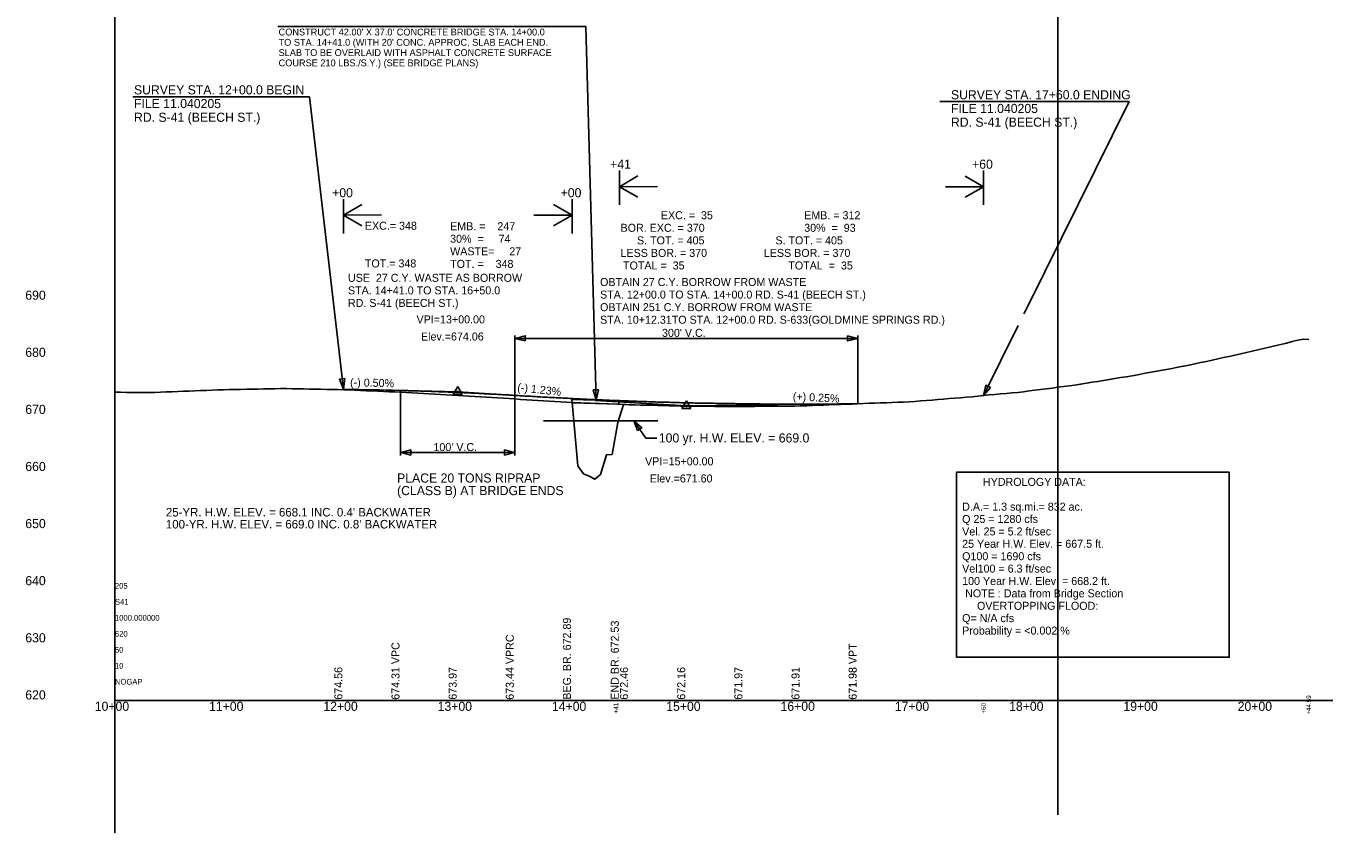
# Model space of a CAD drawing. Extents: x 16382402 to 16388022, y 46194326 to 46202918.
# Drawn here: x 16384274 to 16385409, y 46195513 to 46196212 of the extents above; entities that cross this region are included whole.
import ezdxf

# ---------------------------------------------------------------- set-up
doc = ezdxf.new("R2010")
doc.units = 0
for name, color, linetype in [('Default', 7, 'Continuous'), ('RD_DDB_ElevTX', 7, 'Continuous'), ('RD_DDB_GradeTX', 7, 'Continuous'), ('RD_DDB_Profile_EX', 7, 'Continuous'), ('RD_DDB_Profile_Lbl', 7, 'Continuous'), ('RD_DDB_Profile_PR', 7, 'Continuous'), ('RD_DDB_StaTX', 7, 'Continuous'), ('RD_DDB_StripGrade', 7, 'Continuous'), ('RD_DDB_VCLbl', 7, 'Continuous'), ('RD_EX_Bridge', 7, 'Continuous'), ('RD_GPK_Profile_Cell', 7, 'Continuous'), ('RD_HC_Data', 7, 'Continuous'), ('RD_PD_Final_TX', 7, 'Continuous'), ('RD_TX_Drainage', 7, 'Continuous'), ('RD_TX_Misc1', 7, 'Continuous'), ('RD_TX_Profile', 7, 'Continuous')]:
    doc.layers.add(name, color=color, linetype=linetype)

msp = doc.modelspace()

# ---------------------------------------------------------------- linework, layer by layer
at = {"layer": 'Default'}
for p, q in [((16384792.8, 46196054.9), (16384792.8, 46196084.9)), ((16384808.8, 46196080.2), (16384792.8, 46196070.8)), ((16385095.2, 46196080.1), (16385111.4, 46196070.8)), ((16385111.4, 46196054.9), (16385111.4, 46196084.9)), ((16384826.1, 46196071.1), (16384792.8, 46196070.8)), ((16384808.9, 46196061.6), (16384792.8, 46196070.8)), ((16385078, 46196070.8), (16385111.4, 46196070.8)), ((16385095.2, 46196061.5), (16385111.4, 46196070.8)), ((16384551.4, 46196029.9), (16384551.4, 46196059.9)), ((16384567.4, 46196055.2), (16384551.4, 46196045.8)), ((16384735.2, 46196055.1), (16384751.4, 46196045.8)), ((16384751.4, 46196029.9), (16384751.4, 46196059.9)), ((16384584.7, 46196046.1), (16384551.4, 46196045.8)), ((16384567.5, 46196036.6), (16384551.4, 46196045.8)), ((16384718, 46196045.8), (16384751.4, 46196045.8)), ((16384735.2, 46196036.5), (16384751.4, 46196045.8)), ((16384826.4, 46195865.8), (16384726.4, 46195865.8)), ((16384816, 46195850.6), (16384805.4, 46195865.8)), ((16384825.5, 46195850.7), (16384816, 46195850.6))]:
    msp.add_line(p, q, dxfattribs=at)
at = {"layer": 'RD_DDB_GradeTX'}
for p, q in [((16384571.4, 46195893.1), (16384651.4, 46195891.1)), ((16384731.2, 46195886.2), (16384651.4, 46195891.1)), ((16384771.5, 46195883.7), (16384851.4, 46195878.8)), ((16384931.3, 46195879.8), (16384851.4, 46195878.8))]:
    msp.add_line(p, q, dxfattribs=at)
at = {"layer": 'RD_DDB_Profile_EX'}
for points in [[(16384851.4, 46195878.7), (16384856.4, 46195878.6), (16384861.4, 46195878.6), (16384866.4, 46195878.6), (16384871.4, 46195878.5), (16384876.4, 46195878.3), (16384881.4, 46195878.3), (16384886.4, 46195878.3), (16384891.4, 46195878.3), (16384896.4, 46195878.3), (16384901.4, 46195878.3), (16384906.4, 46195878.4), (16384911.4, 46195878.4), (16384916.4, 46195878.5), (16384921.4, 46195878.5), (16384926.4, 46195878.4), (16384931.4, 46195878.5), (16384936.4, 46195878.6), (16384941.4, 46195878.6), (16384946.4, 46195878.7), (16384951.4, 46195878.8), (16384956.4, 46195879), (16384961.4, 46195879.2), (16384966.4, 46195879.4), (16384971.4, 46195879.6), (16384976.4, 46195879.8), (16384981.4, 46195880), (16384986.4, 46195880.1), (16384991.4, 46195880.3), (16384996.4, 46195880.5), (16385001.4, 46195880.7), (16385006.4, 46195880.9), (16385011.4, 46195881.1), (16385016.4, 46195881.3), (16385021.4, 46195881.4), (16385026.4, 46195881.6), (16385031.4, 46195881.8), (16385036.4, 46195882), (16385041.4, 46195882.2), (16385046.4, 46195882.4), (16385051.4, 46195882.8), (16385056.4, 46195883.2), (16385061.4, 46195883.6), (16385066.4, 46195884), (16385071.4, 46195884.4), (16385076.4, 46195884.8), (16385081.4, 46195885.2), (16385086.4, 46195885.6), (16385091.4, 46195886), (16385096.4, 46195886.4), (16385101.4, 46195886.9), (16385106.4, 46195887.4), (16385111.4, 46195887.9), (16385116.4, 46195888.4), (16385121.4, 46195888.8), (16385126.4, 46195889.3), (16385131.4, 46195889.8), (16385136.4, 46195890.2), (16385141.4, 46195890.7), (16385146.4, 46195891.3), (16385151.4, 46195891.9), (16385156.4, 46195892.6), (16385161.4, 46195893.2), (16385166.4, 46195893.9), (16385171.4, 46195894.5), (16385176.4, 46195895.2), (16385181.4, 46195895.8), (16385186.4, 46195896.4), (16385191.4, 46195897.1), (16385196.4, 46195897.8), (16385201.4, 46195898.7), (16385206.4, 46195899.5), (16385211.4, 46195900.3), (16385216.4, 46195901.1), (16385221.4, 46195901.9), (16385226.4, 46195902.8), (16385231.4, 46195903.6), (16385236.4, 46195904.4), (16385241.4, 46195905.2), (16385246.4, 46195906.1), (16385251.4, 46195907.1), (16385256.4, 46195908), (16385261.4, 46195908.9), (16385266.4, 46195909.9), (16385271.4, 46195910.8), (16385276.4, 46195911.7), (16385281.4, 46195912.7), (16385286.4, 46195913.6), (16385291.4, 46195914.6), (16385296.4, 46195915.7), (16385301.4, 46195916.8), (16385306.4, 46195917.8), (16385311.4, 46195918.9), (16385316.4, 46195920), (16385321.4, 46195921.1), (16385326.4, 46195922.2), (16385331.4, 46195923.3), (16385336.4, 46195924.3), (16385341.4, 46195925.5), (16385346.4, 46195926.7), (16385351.4, 46195927.9)], [(16385351.4, 46195927.9), (16385356.4, 46195929.1), (16385361.4, 46195930.3), (16385366.4, 46195931.5), (16385371.4, 46195932.7), (16385376.4, 46195933.9), (16385381.4, 46195935.1), (16385386.4, 46195936.3), (16385391.4, 46195937.2), (16385395.9, 46195937.1)], [(16384351.4, 46195890.8), (16384356.4, 46195890.8), (16384361.4, 46195890.7), (16384366.4, 46195890.7), (16384371.4, 46195890.7), (16384376.4, 46195890.6), (16384381.4, 46195890.6), (16384386.4, 46195890.7), (16384391.4, 46195890.9), (16384396.4, 46195891.1), (16384401.4, 46195891.2), (16384406.4, 46195891.4), (16384411.4, 46195891.6), (16384416.4, 46195891.8), (16384421.4, 46195892), (16384426.4, 46195892.2), (16384431.4, 46195892.4), (16384436.4, 46195892.6), (16384441.4, 46195892.8), (16384446.4, 46195893), (16384451.4, 46195893.2), (16384456.4, 46195893.3), (16384461.4, 46195893.3), (16384466.4, 46195893.4), (16384471.4, 46195893.5), (16384476.4, 46195893.6), (16384481.4, 46195893.7), (16384486.4, 46195893.8), (16384491.4, 46195893.9), (16384496.4, 46195894), (16384501.4, 46195894), (16384506.4, 46195893.9), (16384511.4, 46195893.8), (16384516.4, 46195893.7), (16384521.4, 46195893.6), (16384526.4, 46195893.5), (16384531.4, 46195893.4), (16384536.4, 46195893.3), (16384541.4, 46195893.2), (16384546.4, 46195893.1), (16384551.4, 46195893), (16384556.4, 46195892.8), (16384561.4, 46195892.6), (16384566.4, 46195892.4), (16384571.4, 46195892.1), (16384576.4, 46195891.9), (16384581.4, 46195891.7), (16384586.4, 46195891.5), (16384591.4, 46195891.3), (16384596.4, 46195891.1), (16384601.4, 46195890.9), (16384606.4, 46195890.6), (16384611.4, 46195890.3), (16384616.4, 46195890), (16384621.4, 46195889.7), (16384626.4, 46195889.4), (16384631.4, 46195889.1), (16384636.4, 46195888.8), (16384641.4, 46195888.5), (16384646.4, 46195888.2), (16384651.4, 46195887.9), (16384656.4, 46195887.8), (16384661.4, 46195887.5), (16384666.4, 46195887.2), (16384671.4, 46195886.8), (16384676.4, 46195886.6), (16384681.4, 46195886.3), (16384686.4, 46195885.9), (16384691.4, 46195885.6), (16384696.4, 46195885.2), (16384701.4, 46195884.9), (16384706.4, 46195884.5), (16384711.4, 46195884.2), (16384716.4, 46195883.9), (16384721.4, 46195883.6), (16384726.4, 46195883.2), (16384731.4, 46195882.9), (16384736.4, 46195882.6), (16384741.4, 46195882.3), (16384746.4, 46195882), (16384751.4, 46195881.7), (16384756.4, 46195826.3), (16384761.4, 46195819.5), (16384766.4, 46195817.3), (16384771.4, 46195814.6), (16384776.4, 46195818.8), (16384781.4, 46195836), (16384786.4, 46195836.4), (16384791.4, 46195864.3), (16384796.4, 46195880.1), (16384801.4, 46195879.9), (16384806.4, 46195879.8), (16384811.4, 46195879.6), (16384816.4, 46195879.5), (16384821.4, 46195879.5), (16384826.4, 46195879.3), (16384831.4, 46195879.2), (16384836.4, 46195879), (16384841.4, 46195878.8), (16384846.4, 46195878.7), (16384851.4, 46195878.7)]]:
    msp.add_lwpolyline(points, dxfattribs=at)
at = {"layer": 'RD_DDB_Profile_PR'}
msp.add_line((16384551.4, 46195893.6), (16384601.4, 46195892.4), dxfattribs=at)
for points in [[(16384601.4, 46195892.4), (16384603.4, 46195892.3), (16384605.4, 46195892.3), (16384607.4, 46195892.2), (16384609.4, 46195892.1), (16384611.4, 46195892.1), (16384613.4, 46195892), (16384615.4, 46195892), (16384617.4, 46195891.9), (16384619.4, 46195891.8), (16384621.4, 46195891.8), (16384623.4, 46195891.7), (16384625.4, 46195891.6), (16384627.4, 46195891.6), (16384629.4, 46195891.5), (16384631.4, 46195891.4), (16384633.4, 46195891.4), (16384635.4, 46195891.3), (16384637.4, 46195891.2), (16384639.4, 46195891.1), (16384641.4, 46195891.1), (16384643.4, 46195891), (16384645.4, 46195890.9), (16384647.4, 46195890.8), (16384649.4, 46195890.7), (16384651.4, 46195890.6), (16384653.4, 46195890.6), (16384655.4, 46195890.5), (16384657.4, 46195890.4), (16384659.4, 46195890.3), (16384661.4, 46195890.2), (16384663.4, 46195890.1), (16384665.4, 46195890), (16384667.4, 46195889.9), (16384669.4, 46195889.8), (16384671.4, 46195889.7), (16384673.4, 46195889.6), (16384675.4, 46195889.5), (16384677.4, 46195889.4), (16384679.4, 46195889.3), (16384681.4, 46195889.2), (16384683.4, 46195889.1), (16384685.4, 46195889), (16384687.4, 46195888.8), (16384689.4, 46195888.7), (16384691.4, 46195888.6), (16384693.4, 46195888.5), (16384695.4, 46195888.4), (16384697.4, 46195888.3), (16384699.4, 46195888.1), (16384701.4, 46195888)], [(16384701.4, 46195888), (16384707.4, 46195887.7), (16384713.4, 46195887.3), (16384719.4, 46195887), (16384725.4, 46195886.6), (16384731.4, 46195886.3), (16384737.4, 46195886), (16384743.4, 46195885.7), (16384749.4, 46195885.4), (16384755.4, 46195885.1), (16384761.4, 46195884.8), (16384767.4, 46195884.5), (16384773.4, 46195884.2), (16384779.4, 46195884), (16384785.4, 46195883.7), (16384791.4, 46195883.5), (16384797.4, 46195883.3), (16384803.4, 46195883), (16384809.4, 46195882.8), (16384815.4, 46195882.6), (16384821.4, 46195882.4), (16384827.4, 46195882.2), (16384833.4, 46195882.1), (16384839.4, 46195881.9), (16384845.4, 46195881.7), (16384851.4, 46195881.6), (16384857.4, 46195881.4), (16384863.4, 46195881.3), (16384869.4, 46195881.2), (16384875.4, 46195881.1), (16384881.4, 46195881), (16384887.4, 46195880.9), (16384893.4, 46195880.8), (16384899.4, 46195880.7), (16384905.4, 46195880.6), (16384911.4, 46195880.6), (16384917.4, 46195880.5), (16384923.4, 46195880.5), (16384929.4, 46195880.4), (16384935.4, 46195880.4), (16384941.4, 46195880.4), (16384947.4, 46195880.4), (16384953.4, 46195880.4), (16384959.4, 46195880.4), (16384965.4, 46195880.4), (16384971.4, 46195880.4), (16384977.4, 46195880.5), (16384983.4, 46195880.5), (16384989.4, 46195880.6), (16384995.4, 46195880.6), (16385001.4, 46195880.7)]]:
    msp.add_spline(points, degree=3, dxfattribs=at)
at = {"layer": 'RD_DDB_VCLbl'}
for p, q in [((16384701.4, 46195940.5), (16384701.4, 46195888)), ((16385001.4, 46195940.5), (16385001.4, 46195880.7)), ((16384701.4, 46195938), (16385001.4, 46195938)), ((16384601.4, 46195835.5), (16384601.4, 46195892.4)), ((16384701.4, 46195835.5), (16384701.4, 46195888)), ((16384601.4, 46195838), (16384701.4, 46195838))]:
    msp.add_line(p, q, dxfattribs=at)
at = {"layer": 'RD_EX_Bridge'}
for p, q in [((16384493.9, 46196211), (16384763.3, 46196211)), ((16384772.5, 46195883.9), (16384763.3, 46196211)), ((16384751.3, 46195884.5), (16384792.4, 46195883.4)), ((16384751.4, 46195881.5), (16384751.3, 46195884.5)), ((16384792.4, 46195883.4), (16384792.4, 46195880.3)), ((16384792.4, 46195880.3), (16384751.4, 46195881.5))]:
    msp.add_line(p, q, dxfattribs=at)
at = {"layer": 'RD_GPK_Profile_Cell'}
for p, q in [((16384351.4, 46195620.8), (16384351.4, 46196870.8)), ((16385176.4, 46196770.8), (16385176.4, 46195520.8)), ((16384351.4, 46195620.8), (16385651.4, 46195620.8)), ((16384351.4, 46195620.8), (16384351.4, 46194370.8))]:
    msp.add_line(p, q, dxfattribs=at)
at = {"layer": 'RD_HC_Data'}
for p, q in [((16384647.4, 46195888.8), (16384651.4, 46195895.7)), ((16384651.4, 46195895.7), (16384655.3, 46195888.8)), ((16384647.4, 46195888.8), (16384655.3, 46195888.8)), ((16384847.4, 46195876.5), (16384851.4, 46195883.4)), ((16384851.4, 46195883.4), (16384855.3, 46195876.5)), ((16384847.4, 46195876.5), (16384855.3, 46195876.5))]:
    msp.add_line(p, q, dxfattribs=at)
for centre in [(16384651.4, 46195891.1), (16384851.4, 46195878.8)]:
    msp.add_circle(centre, 0.529, dxfattribs=at)
at = {"layer": 'RD_PD_Final_TX'}
for p, q in [((16384367.2, 46196149.5), (16384521.8, 46196149.5)), ((16384551.3, 46195893.6), (16384521.8, 46196149.5)), ((16385073.3, 46196145.3), (16385238.9, 46196145.3)), ((16385150.2, 46195966.3), (16385238.9, 46196145.3)), ((16385146.8, 46195959.4), (16385150.2, 46195966.3)), ((16385111.4, 46195887.9), (16385141.8, 46195949.3))]:
    msp.add_line(p, q, dxfattribs=at)
at = {"layer": 'RD_TX_Drainage'}
for points in [[(16384710.4, 46195935.8), (16384701.4, 46195938), (16384710.4, 46195940.3)], [(16384992.4, 46195940.3), (16385001.4, 46195938), (16384992.4, 46195935.8)], [(16384552.5, 46195902.8), (16384551.3, 46195893.6), (16384548, 46195902.3)], [(16385117.4, 46195894.9), (16385111.4, 46195887.9), (16385113.3, 46195896.9)], [(16384774.5, 46195893), (16384772.5, 46195883.9), (16384770, 46195892.9)], [(16384808.7, 46195857.2), (16384805.3, 46195865.8), (16384812.3, 46195859.7)], [(16384610.4, 46195835.8), (16384601.4, 46195838), (16384610.4, 46195840.3)], [(16384692.4, 46195840.3), (16384701.4, 46195838), (16384692.4, 46195835.8)]]:
    msp.add_lwpolyline(points, close=True, dxfattribs=at)
at = {"layer": 'RD_TX_Misc1'}
msp.add_line((16384751.4, 46195881.7), (16384798.9, 46195880), dxfattribs=at)
at = {"layer": 'RD_TX_Profile'}
msp.add_lwpolyline([(16385087.7, 46195658.7), (16385326.4, 46195658.7), (16385326.4, 46195820.8), (16385087.7, 46195820.8)], close=True, dxfattribs=at)

# ---------------------------------------------------------------- texts
at = {"layer": 'Default'}
for s, height, p in [('+41', 8, (16384784.7, 46196086.5)), ('+60', 8, (16385101.4, 46196086.5)), ('+00', 8, (16384541.5, 46196061.5)), ('+00', 8, (16384741.4, 46196061.5)), ('EXC. =  35', 7, (16384829.1, 46196042.3)), ('EMB. = 312', 7, (16384954.5, 46196042.3)), ('EXC.= 348', 7, (16384570.1, 46196033.1)), ('EMB. =    247', 7, (16384644.7, 46196032.7)), ('BOR. EXC. = 370', 7, (16384793.8, 46196031.3)), ('30%  =  93', 7, (16384954.5, 46196031.3)), ('30%  =     74', 7, (16384644.7, 46196021.7)), ('S. TOT. = 405', 7, (16384808.2, 46196020.3)), (' S. TOT. = 405', 7, (16384926.7, 46196020.3)), ('TOT.= 348', 7, (16384570.1, 46196000.1)), ('WASTE=     27', 7, (16384644.7, 46196010.7)), ('LESS BOR. = 370', 7, (16384793.8, 46196009.3)), ('LESS BOR. = 370', 7, (16384919.2, 46196009.3)), ('TOT. =    348', 7, (16384644.7, 46195999.7)), ('      TOTAL =  35', 7, (16384780.4, 46195998.3)), ('TOTAL  =  35', 7, (16384940.6, 46195998.3)), ('USE  27 C.Y. WASTE AS BORROW', 7, (16384555.3, 46195987.5)), ('OBTAIN 27 C.Y. BORROW FROM WASTE', 7, (16384775.9, 46195983.8)), ('STA. 14+41.0 TO STA. 16+50.0', 7, (16384555.3, 46195976.5)), ('STA. 12+00.0 TO STA. 14+00.0 RD. S-41 (BEECH ST.)', 7, (16384775.9, 46195972.8)), ('RD. S-41 (BEECH ST.)', 7, (16384555.3, 46195965.5)), ('OBTAIN 251 C.Y. BORROW FROM WASTE', 7, (16384775.9, 46195961.8)), ('STA. 10+12.31TO STA. 12+00.0 RD. S-633(GOLDMINE SPRINGS RD.)', 7, (16384775.9, 46195950.8)), ('100 yr. H.W. ELEV. = 669.0', 8, (16384827.3, 46195846.8)), ('PLACE 20 TONS RIPRAP', 8, (16384598.3, 46195811.7)), ('(CLASS B) AT BRIDGE ENDS', 8, (16384598.3, 46195800.7)), ("25-YR. H.W. ELEV. = 668.1 INC. 0.4' BACKWATER", 7.5, (16384396, 46195782)), ("100-YR. H.W. ELEV. = 669.0 INC. 0.8' BACKWATER", 7.5, (16384396, 46195771.5))]:
    msp.add_text(s, height=height, dxfattribs=at).set_placement(p)
at = {"layer": 'RD_DDB_ElevTX'}
for s, p in [('690', (16384273, 46195971.8)), ('680', (16384273, 46195921.8)), ('670', (16384273, 46195871.8)), ('660', (16384273, 46195821.8)), ('650', (16384273, 46195771.8)), ('640', (16384273, 46195721.8)), ('630', (16384273, 46195671.8)), ('620', (16384273, 46195621.8))]:
    msp.add_text(s, height=8, dxfattribs=at).set_placement(p)
at = {"layer": 'RD_DDB_GradeTX'}
for s, rotation, p in [('(-) 0.50%', 358.5559, (16384557.1, 46195896.1)), ('(-) 1.23%', 353.6694, (16384703.2, 46195891.8)), ('(+) 0.25%', 357.0067, (16384944.4, 46195883.8))]:
    msp.add_text(s, height=7, rotation=rotation, dxfattribs=at).set_placement(p)
at = {"layer": 'RD_DDB_Profile_Lbl'}
for s, p in [('VPI=13+00.00', (16384615.3, 46195951.1)), ('Elev.=674.06', (16384619.2, 46195936.1)), ('VPI=15+00.00', (16384815.3, 46195826.8)), ('Elev.=671.60', (16384819.4, 46195811.8))]:
    msp.add_text(s, height=7, dxfattribs=at).set_placement(p)
at = {"layer": 'RD_DDB_StaTX'}
for s, p in [('+44.59', (16385397.9, 46195608.4)), ('+41', (16384791.8, 46195609.5)), ('+60', (16385113.4, 46195609.4))]:
    msp.add_text(s, height=4, rotation=90, dxfattribs=at).set_placement(p)
for s, p in [('10+00', (16384333.8, 46195611.8)), ('11+00', (16384433.8, 46195611.8)), ('12+00', (16384533.8, 46195611.8)), ('13+00', (16384633.8, 46195611.8)), ('14+00', (16384733.8, 46195611.8)), ('15+00', (16384833.8, 46195611.8)), ('16+00', (16384933.8, 46195611.8)), ('17+00', (16385033.8, 46195611.8)), ('18+00', (16385133.8, 46195611.8)), ('19+00', (16385233.8, 46195611.8)), ('20+00', (16385333.8, 46195611.8))]:
    msp.add_text(s, height=8, dxfattribs=at).set_placement(p)
at = {"layer": 'RD_DDB_StripGrade'}
for s, p in [('BEG. BR. 672.89', (16384750.4, 46195621.6)), ('END BR. 672.53', (16384792.3, 46195621.6)), ('673.44 VPRC', (16384700.4, 46195621.5)), ('674.31 VPC', (16384600.4, 46195621.5)), ('671.98 VPT', (16385000.4, 46195621.5)), ('674.56', (16384550.4, 46195621.6)), ('673.97', (16384650.4, 46195621.6)), ('672.46', (16384800.4, 46195621.6)), ('672.16', (16384850.4, 46195621.6)), ('671.97', (16384900.4, 46195621.6)), ('671.91', (16384950.4, 46195621.6)), ('671.98', (16385000.4, 46195621.6))]:
    msp.add_text(s, height=7, rotation=90, dxfattribs=at).set_placement(p)
at = {"layer": 'RD_DDB_VCLbl'}
for s, p in [("300' V.C.", (16384830.1, 46195939.3)), ("100' V.C.", (16384630.1, 46195839.3))]:
    msp.add_text(s, height=7, dxfattribs=at).set_placement(p)
at = {"layer": 'RD_EX_Bridge'}
for s, p in [("TO STA. 14+41.0 (WITH 20' CONC. APPROC, SLAB EACH END.", (16384494.6, 46196194.2)), ("CONSTRUCT 42.00' X 37.0' CONCRETE BRIDGE STA. 14+00.0 ", (16384494.6, 46196203.2)), ('SLAB TO BE OVERLAID WITH ASPHALT CONCRETE SURFACE ', (16384494.6, 46196185.2)), ('COURSE 210 LBS./S.Y.) (SEE BRIDGE PLANS)', (16384494.6, 46196176.2))]:
    msp.add_text(s, height=6, dxfattribs=at).set_placement(p)
at = {"layer": 'RD_GPK_Profile_Cell'}
for s, p in [('205', (16384351.4, 46195718.8)), ('S41', (16384351.4, 46195704.8)), ('1000.000000', (16384351.4, 46195690.8)), ('620', (16384351.4, 46195676.8)), ('50', (16384351.4, 46195662.8)), ('10', (16384351.4, 46195648.8)), ('NOGAP', (16384351.4, 46195634.8))]:
    msp.add_text(s, height=5, dxfattribs=at).set_placement(p)
at = {"layer": 'RD_PD_Final_TX'}
for s, p in [('SURVEY STA. 12+00.0 BEGIN', (16384368.1, 46196151.6)), ('SURVEY STA. 17+60.0 ENDING', (16385082.9, 46196147.3)), ('FILE 11.040205', (16384368.1, 46196139.6)), ('FILE 11.040205', (16385082.9, 46196135.3)), ('RD. S-41 (BEECH ST.)', (16384368.1, 46196127.6)), ('RD. S-41 (BEECH ST.)', (16385082.9, 46196123.3))]:
    msp.add_text(s, height=8, dxfattribs=at).set_placement(p)
at = {"layer": 'RD_TX_Profile'}
for s, p in [('       HYDROLOGY DATA:', (16385092.7, 46195808.8)), ('D.A.= 1.3 sq.mi.= 832 ac.', (16385092.7, 46195787.1)), ('Q 25 = 1280 cfs', (16385092.7, 46195776.3)), ('Vel. 25 = 5.2 ft/sec', (16385092.7, 46195765.4)), ('25 Year H.W. Elev. = 667.5 ft.', (16385092.7, 46195754.6)), ('Q100 = 1690 cfs', (16385092.7, 46195743.7)), ('Vel100 = 6.3 ft/sec', (16385092.7, 46195732.9)), ('100 Year H.W. Elev. = 668.2 ft.', (16385092.7, 46195722)), (' NOTE : Data from Bridge Section', (16385092.7, 46195711.2)), ('     OVERTOPPING FLOOD:', (16385092.7, 46195700.3)), ('Q= N/A cfs', (16385092.7, 46195689.5)), ('Probability = <0.002 %', (16385092.7, 46195678.6))]:
    msp.add_text(s, height=7, dxfattribs=at).set_placement(p)

doc.saveas('drawing.dxf')
